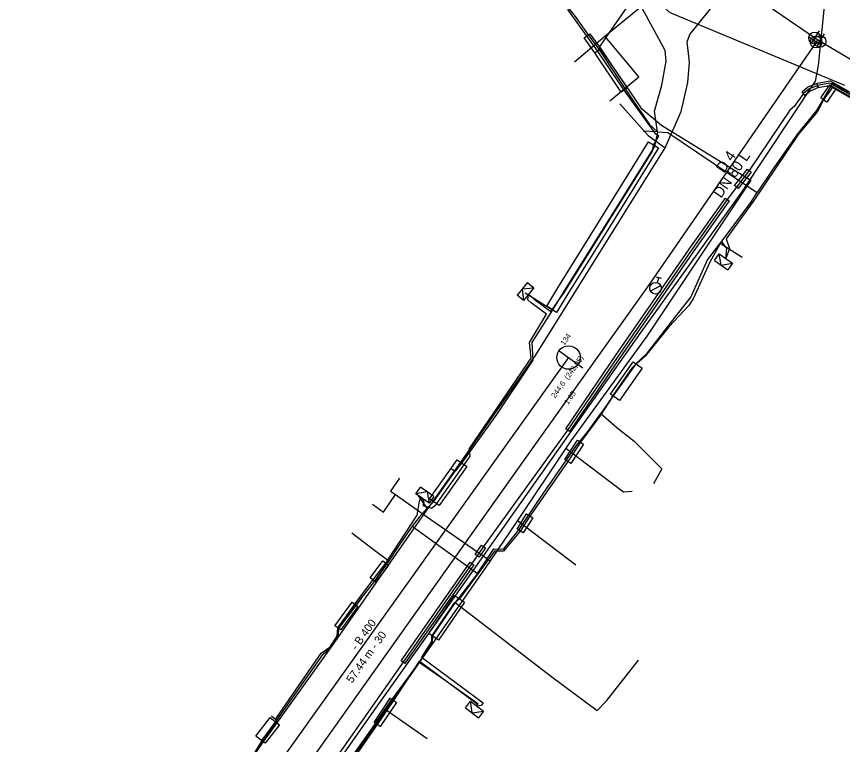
# Model space of a CAD drawing. Extents: x -600636 to -600148, y -1203980 to -1203569.
# Drawn here: x -600384.3 to -600313.9, y -1203740.1 to -1203678.1 of the extents above; entities that cross this region are included whole.
import ezdxf

# ---------------------------------------------------------------- set-up
doc = ezdxf.new("R2010")
doc.units = 0
for name, color, linetype in [('Cetin zam průběh', 7, 'Continuous'), ('EON podzemní NN', 7, 'Continuous'), ('EON podzemní VN', 7, 'Continuous'), ('GasNet NTL', 7, 'Continuous'), ('Implicitní', 7, 'Continuous'), ('VaK Břeclav_kanalizace', 7, 'Continuous'), ('Vak Břeclav_vodovod', 7, 'Continuous'), ('Vrstva 9', 7, 'Continuous')]:
    doc.layers.add(name, color=color, linetype=linetype)

# ---------------------------------------------------------------- blocks, each defined once
blk = doc.blocks.new('NN630')
at = {"layer": 'Vrstva 9'}
for points in [[(-0.003, -0.7), (-0.703, 0)], [(-0.703, -0.7), (-0.703, 0), (0.697, 0), (0.697, -0.7)], [(-0.703, -0.7), (0.697, -0.7)], [(-0.003, -0.7), (0.697, 0)]]:
    blk.add_lwpolyline(points, dxfattribs=at)
blk = doc.blocks.new('MoSymbol 2')
at = {"layer": 'Implicitní'}
blk.add_line((0, 0.0005), (0, -0.00075), dxfattribs=at)
blk.add_circle((0, 0), 0.0005, dxfattribs=at)
blk = doc.blocks.new('MoSymbol 3')
at = {"layer": 'Implicitní'}
for p, q in [((-0.000225, 0.00095), (0.000225, 0.00095)), ((0, 0.00095), (0, 0.0005)), ((-0.000365, -0.000365), (0.000365, 0.000365))]:
    blk.add_line(p, q, dxfattribs=at)
blk.add_circle((0, 0), 0.0005, dxfattribs=at)

msp = doc.modelspace()

# ---------------------------------------------------------------- linework, layer by layer
at = {"layer": 'Cetin zam průběh'}
for points in [[(-600329.02, -1203689.27), (-600327.65, -1203686.16), (-600327.07, -1203683.69), (-600326.94, -1203681.95), (-600327.13, -1203680.22), (-600326.9, -1203679.6), (-600320.9, -1203672.11), (-600319.87, -1203671.25), (-600312.14, -1203676.45), (-600307.68, -1203679.27), (-600299.7, -1203684.11), (-600292.77, -1203688.32), (-600284.45, -1203693.32), (-600273.46, -1203699.98), (-600262.73, -1203706.4), (-600257.97, -1203709.2), (-600243.31, -1203717.93), (-600240.56, -1203720.13), (-600238.73, -1203718.32)], [(-600341.99, -1203672.1), (-600339.02, -1203675.1), (-600336.67, -1203678.06), (-600335.49, -1203679.73), (-600334.6, -1203680.94), (-600332.38, -1203684.29), (-600330.34, -1203687.27), (-600329.66, -1203687.89)], [(-600329.66, -1203687.89), (-600329.92, -1203686.15), (-600329.28, -1203683.93), (-600328.92, -1203681.87), (-600329, -1203680.95), (-600330.94, -1203677.41), (-600331.52, -1203676.9)], [(-600335.49, -1203679.73), (-600334.6, -1203680.94)], [(-600334.6, -1203680.94), (-600332.38, -1203684.29)], [(-600291.91, -1203697.34), (-600294.89, -1203695.51), (-600296.18, -1203694.98), (-600299.85, -1203692.83), (-600301.61, -1203691.58), (-600303.13, -1203690.66), (-600304.86, -1203689.65), (-600306.01, -1203688.96), (-600312.14, -1203685.36), (-600314.73, -1203683.76), (-600316.09, -1203686.08)], [(-600332.86, -1203685.5), (-600330.45, -1203688.2), (-600329.02, -1203689.27)], [(-600316.09, -1203686.08), (-600317.72, -1203688.07), (-600319.94, -1203691.26), (-600321.15, -1203693.08)], [(-600329.66, -1203687.89), (-600329.93, -1203689.16), (-600334.23, -1203696.05), (-600337.61, -1203701.47), (-600338.62, -1203703.09)], [(-600329.66, -1203687.89), (-600330.88, -1203687.85)], [(-600329.66, -1203687.89), (-600328.78, -1203687.96), (-600322.25, -1203692.35), (-600321.15, -1203693.08)], [(-600328.78, -1203687.96), (-600322.25, -1203692.35)], [(-600448.32, -1203764.77), (-600445.41, -1203766.9), (-600434.97, -1203774.92), (-600422.32, -1203783.12), (-600413.93, -1203789.04), (-600405.18, -1203794.93), (-600400.25, -1203797.98), (-600398.96, -1203798.36), (-600397.12, -1203797.36), (-600388.96, -1203781.95), (-600378.33, -1203762.13), (-600375.93, -1203758.23), (-600373.1, -1203754.01), (-600370.24, -1203749.96), (-600363.35, -1203740.04), (-600357.38, -1203731.69), (-600349.33, -1203720.15), (-600345.8, -1203715.19), (-600340.07, -1203706.96), (-600329.02, -1203689.27)], [(-600329.93, -1203689.16), (-600334.23, -1203696.05)], [(-600324.32, -1203697.42), (-600321.71, -1203693.92), (-600321.15, -1203693.08)], [(-600324.32, -1203697.42), (-600325.2, -1203699.01), (-600326.63, -1203702.13)], [(-600322.43, -1203698.61), (-600324.32, -1203697.42)], [(-600340.96, -1203701.64), (-600338.62, -1203703.09)], [(-600337.61, -1203701.47), (-600338.62, -1203703.09)], [(-600326.63, -1203702.13), (-600327, -1203702.72), (-600328.66, -1203704.49), (-600330.72, -1203707.02), (-600331.77, -1203707.97), (-600333.55, -1203710.56), (-600334.48, -1203711.92)], [(-600338.62, -1203703.09), (-600340.39, -1203705.86), (-600340.29, -1203707.36), (-600343.45, -1203712.08), (-600346.39, -1203716.15), (-600346.93, -1203716.85)], [(-600333.55, -1203710.56), (-600331.77, -1203707.97)], [(-600345.02, -1203725.57), (-600343.61, -1203723.45), (-600342.8, -1203723.5), (-600341.47, -1203721.81), (-600339.64, -1203719.08), (-600336.56, -1203714.64), (-600335.67, -1203713.53), (-600334.48, -1203711.92)], [(-600334.48, -1203711.92), (-600333.14, -1203713.1), (-600331.65, -1203714.28), (-600329.3, -1203716.65), (-600330, -1203717.93)], [(-600348.77, -1203719.46), (-600346.93, -1203716.85), (-600346.39, -1203716.15)], [(-600347.22, -1203716.65), (-600346.93, -1203716.85)], [(-600349.3, -1203719.98), (-600348.77, -1203719.46), (-600346.93, -1203716.85)], [(-600349.3, -1203719.98), (-600350.05, -1203718.94)], [(-600349.3, -1203719.98), (-600349.98, -1203720.75), (-600350.59, -1203721.54)], [(-600350.59, -1203721.54), (-600351.64, -1203723.07)], [(-600350.59, -1203721.54), (-600345.02, -1203725.57)], [(-600350.59, -1203721.54), (-600345.02, -1203725.57)], [(-600355.72, -1203722.09), (-600353.92, -1203723.48), (-600352.59, -1203724.49)], [(-600351.64, -1203723.07), (-600352.59, -1203724.49)], [(-600362.14, -1203738.07), (-600358.19, -1203732.44), (-600357.54, -1203731.91), (-600356.89, -1203730.92), (-600356.8, -1203730.18), (-600354.93, -1203727.69), (-600353.8, -1203726.24), (-600352.59, -1203724.49)], [(-600352.59, -1203724.49), (-600353.8, -1203726.24)], [(-600345.02, -1203725.57), (-600346.92, -1203728.04)], [(-600354.93, -1203727.69), (-600356.8, -1203730.18)], [(-600346.92, -1203728.04), (-600348.83, -1203730.83), (-600348.92, -1203731.44), (-600349.98, -1203733.11)], [(-600348.83, -1203730.83), (-600346.92, -1203728.04)], [(-600346.92, -1203728.04), (-600338.68, -1203734.38), (-600334.81, -1203737.25), (-600333.97, -1203736.39), (-600331.29, -1203732.95)], [(-600349.98, -1203733.11), (-600352.35, -1203736.35), (-600353.65, -1203738.25), (-600357.31, -1203743.38), (-600359.31, -1203746.17), (-600359.98, -1203746.53), (-600361.18, -1203748.34)], [(-600349.98, -1203733.11), (-600348.14, -1203734.39), (-600346.78, -1203735.36), (-600344.99, -1203736.64), (-600345.13, -1203736.85)], [(-600353.65, -1203738.25), (-600352.35, -1203736.35)], [(-600362.59, -1203737.71), (-600362.14, -1203738.07)], [(-600371.33, -1203751.67), (-600367.69, -1203746.37), (-600365.25, -1203742.89), (-600363.56, -1203740.1), (-600363.39, -1203739.78), (-600362.14, -1203738.07)], [(-600362.14, -1203738.07), (-600363.39, -1203739.78)], [(-600365.25, -1203742.89), (-600363.56, -1203740.1)]]:
    msp.add_lwpolyline(points, dxfattribs=at)
at = {"layer": 'EON podzemní NN'}
for points in [[(-600364.409, -1203741.504), (-600363.365, -1203739.833), (-600362.171, -1203738.261), (-600362.154, -1203737.878), (-600358.34, -1203732.37), (-600357.58, -1203731.83), (-600356.98, -1203730.9), (-600356.92, -1203730.2), (-600355.15, -1203727.74), (-600353.93, -1203726.13), (-600352.83, -1203724.67), (-600352.64, -1203724.36), (-600350.16, -1203720.58), (-600349.974, -1203719.405), (-600349.918, -1203719.261), (-600349.71, -1203719.17), (-600349.578, -1203719.49), (-600349.688, -1203719.771), (-600348.944, -1203719.986), (-600348.538, -1203719.669), (-600346.141, -1203716.287), (-600345.646, -1203715.55), (-600345.687, -1203714.9), (-600340.43, -1203707.19), (-600340.58, -1203705.85), (-600339.125, -1203703.456), (-600340.432, -1203702.472), (-600340.728, -1203702.213), (-600340.66, -1203701.74), (-600340.18, -1203702.162), (-600338.756, -1203703.234), (-600337.583, -1203701.581), (-600330.091, -1203689.555), (-600330, -1203689.03), (-600329.55, -1203688.27), (-600329.79, -1203688.1), (-600332.51, -1203684.34), (-600334.77, -1203681), (-600337.32, -1203677.47)], [(-600300.1, -1203693.14), (-600300.09, -1203692.82), (-600302.356, -1203691.251), (-600303.624, -1203690.511), (-600305.35, -1203689.5), (-600311.54, -1203685.86), (-600314.7, -1203684.06), (-600315.49, -1203685.17), (-600316.007, -1203686.155), (-600317.63, -1203688.11), (-600321.5, -1203693.84), (-600323.385, -1203696.438)], [(-600323.385, -1203696.438), (-600323.817, -1203697.034), (-600323.521, -1203697.85), (-600323.824, -1203698.698), (-600323.753, -1203697.835), (-600324.207, -1203697.234), (-600325.017, -1203698.307)], [(-600325.017, -1203698.307), (-600325.386, -1203698.796), (-600326.82, -1203701.97), (-600328.814, -1203704.512), (-600330.617, -1203706.864), (-600331.49, -1203707.646), (-600333.526, -1203710.518), (-600334.519, -1203712.072), (-600336.22, -1203714.37), (-600337.32, -1203716), (-600340.56, -1203720.66), (-600341.38, -1203721.95), (-600342.79, -1203723.669), (-600343.55, -1203723.65), (-600346.55, -1203727.73), (-600347.052, -1203728.137), (-600348.942, -1203730.911), (-600348.932, -1203731.374), (-600349.779, -1203732.697), (-600344.525, -1203736.593), (-600344.695, -1203736.832), (-600345.04, -1203736.88), (-600345.051, -1203736.7), (-600349.996, -1203733.034), (-600352.18, -1203736.39), (-600353.56, -1203738.45), (-600357.2, -1203743.67)]]:
    msp.add_lwpolyline(points, dxfattribs=at)
for points in [[(-600335.925, -1203679.884), (-600335.429, -1203679.529), (-600334.505, -1203680.82), (-600335.011, -1203681.161)], [(-600335.011, -1203681.161), (-600334.505, -1203680.82), (-600332.249, -1203684.162), (-600332.754, -1203684.503)], [(-600314.955, -1203683.887), (-600314.443, -1203684.24), (-600315.216, -1203685.361), (-600315.728, -1203685.008)], [(-600330.418, -1203688.745), (-600329.562, -1203689.263), (-600333.895, -1203696.258), (-600337.308, -1203701.715), (-600338.28, -1203703.313), (-600339.108, -1203702.752), (-600338.16, -1203701.191), (-600334.737, -1203695.718)], [(-600331.743, -1203707.518), (-600330.967, -1203708.065), (-600332.905, -1203710.817), (-600333.681, -1203710.271)], [(-600336.476, -1203714.193), (-600335.962, -1203714.539), (-600337.061, -1203716.17), (-600337.571, -1203715.829)], [(-600346.738, -1203715.862), (-600345.921, -1203716.438), (-600348.279, -1203719.778), (-600349.094, -1203719.203)], [(-600340.822, -1203720.482), (-600340.299, -1203720.816), (-600341.122, -1203722.104), (-600341.641, -1203721.775)], [(-600353.075, -1203724.495), (-600352.596, -1203724.858), (-600353.693, -1203726.306), (-600354.171, -1203725.944)], [(-600355.717, -1203728.014), (-600355.226, -1203728.369), (-600356.679, -1203730.377), (-600357.17, -1203730.022)], [(-600346.964, -1203727.443), (-600346.136, -1203728.005), (-600348.334, -1203731.245), (-600349.154, -1203730.692)], [(-600352.459, -1203736.202), (-600351.936, -1203736.553), (-600353.317, -1203738.612), (-600353.836, -1203738.265)], [(-600362.708, -1203737.856), (-600361.914, -1203738.463), (-600363.116, -1203740.036), (-600363.911, -1203739.429)]]:
    msp.add_lwpolyline(points, close=True, dxfattribs=at)
at = {"layer": 'EON podzemní VN'}
for points in [[(-600366.95, -1203635.593), (-600366.181, -1203636.795), (-600358.381, -1203643.411), (-600344.954, -1203653.759), (-600330.827, -1203664.425), (-600321.645, -1203670.963), (-600317.713, -1203673.458), (-600315.791, -1203674.896), (-600315.293, -1203675.777), (-600315.944, -1203682.246), (-600316.226, -1203683.581), (-600322.501, -1203693.042), (-600331.079, -1203704.985), (-600348.911, -1203730.288), (-600354.208, -1203737.743), (-600361.516, -1203748.136), (-600365.138, -1203753.003), (-600368.824, -1203758.254), (-600375.091, -1203769.039), (-600381.398, -1203780.278), (-600382.49, -1203782.6), (-600383.25, -1203783.59)], [(-600313.007, -1203684.869), (-600314.967, -1203683.759), (-600316.007, -1203683.949), (-600316.757, -1203684.269), (-600317.207, -1203684.639), (-600317.997, -1203685.729), (-600318.367, -1203686.039), (-600321.837, -1203691.209), (-600322.927, -1203692.609), (-600323.707, -1203693.669), (-600326.587, -1203697.729), (-600333.047, -1203707.069), (-600337.327, -1203713.329), (-600344.497, -1203723.269), (-600345.047, -1203724.049), (-600345.487, -1203724.709), (-600351.367, -1203733.129), (-600357.517, -1203741.909)]]:
    msp.add_lwpolyline(points, dxfattribs=at)
for points in [[(-600313.105, -1203685.043), (-600315.002, -1203683.969), (-600315.971, -1203684.146), (-600316.043, -1203683.752), (-600314.931, -1203683.549), (-600312.908, -1203684.695)], [(-600316.085, -1203683.765), (-600315.928, -1203684.133), (-600316.652, -1203684.442), (-600317.08, -1203684.793), (-600317.334, -1203684.484), (-600316.861, -1203684.096)], [(-600321.994, -1203691.086), (-600321.679, -1203691.332), (-600322.769, -1203692.732), (-600323.084, -1203692.486)], [(-600323.87, -1203693.553), (-600323.543, -1203693.785), (-600326.423, -1203697.844), (-600332.882, -1203707.182), (-600337.162, -1203713.442), (-600337.492, -1203713.216), (-600333.211, -1203706.956), (-600326.75, -1203697.614)], [(-600344.66, -1203723.154), (-600344.333, -1203723.384), (-600344.883, -1203724.164), (-600345.21, -1203723.934)], [(-600345.651, -1203724.594), (-600345.323, -1203724.823), (-600351.203, -1203733.243), (-600351.531, -1203733.014)]]:
    msp.add_lwpolyline(points, close=True, dxfattribs=at)
at = {"layer": 'GasNet NTL'}
for points in [[(-600309.24, -1203678.67), (-600322.08, -1203669.74), (-600324.1, -1203669.99), (-600324.38, -1203670.02), (-600324.57, -1203670.3), (-600329.11, -1203676.87), (-600329.27, -1203677.14), (-600328.72, -1203677.64), (-600328.46, -1203677.78), (-600313.71, -1203683.92)], [(-600331.63, -1203676.31), (-600333.84, -1203679.52), (-600334.07, -1203679.86), (-600334.63, -1203680.67), (-600332.29, -1203684.08), (-600331.07, -1203685.85), (-600329.31, -1203687.34), (-600321.69, -1203692.03)], [(-600330.12, -1203676.43), (-600333.84, -1203679.52), (-600334.14, -1203679.77)], [(-600334.14, -1203679.77), (-600336.75, -1203681.95)], [(-600334.14, -1203679.77), (-600331.26, -1203683.23), (-600333.72, -1203685.28)], [(-600321.69, -1203692.03), (-600330.58, -1203705.33), (-600337.06, -1203714.26), (-600337.47, -1203714.88), (-600341.61, -1203721.03), (-600343.93, -1203724.48), (-600344.29, -1203725.01), (-600352.8, -1203737.19), (-600355.42, -1203740.94), (-600356.36, -1203742.04), (-600356.56, -1203742.28), (-600357.37, -1203743.06), (-600358.82, -1203744.14), (-600359.04, -1203744.31), (-600359.16, -1203744.4), (-600365.08, -1203752.77), (-600365.18, -1203752.95), (-600368.57, -1203759.1), (-600375.05, -1203770.85), (-600375.18, -1203771.08)], [(-600337.47, -1203714.88), (-600332.57, -1203718.61), (-600331.83, -1203718.55)], [(-600351.67, -1203717.44), (-600352.44, -1203718.54), (-600352.01, -1203718.84)], [(-600353.98, -1203719.66), (-600353.04, -1203720.32), (-600352.01, -1203718.84)], [(-600352.01, -1203718.84), (-600349.36, -1203720.69), (-600344.44, -1203724.12), (-600343.93, -1203724.48)], [(-600341.61, -1203721.03), (-600336.63, -1203724.81)], [(-600352.8, -1203737.19), (-600349.31, -1203739.63)]]:
    msp.add_lwpolyline(points, dxfattribs=at)
at = {"layer": 'VaK Břeclav_kanalizace'}
msp.add_line((-600337.248, -1203707.145), (-600370.65, -1203753.88), dxfattribs=at)
at = {"layer": 'Vak Břeclav_vodovod'}
for p, q in [((-600316.022, -1203680.054), (-600316.256, -1203679.894)), ((-600316.022, -1203680.054), (-600316.133, -1203680.243)), ((-600315.791, -1203680.191), (-600316.022, -1203680.054)), ((-600316.133, -1203680.243), (-600330.382, -1203700.926))]:
    msp.add_line(p, q, dxfattribs=at)
for points in [[(-600316.256, -1203679.894), (-600332.434, -1203668.792), (-600354.837, -1203651.734), (-600377.846, -1203634.299)], [(-600236.89, -1203728.365), (-600242.377, -1203724.953), (-600264, -1203711.729), (-600288.949, -1203696.473), (-600297.916, -1203690.812), (-600315.791, -1203680.191)], [(-600330.382, -1203700.926), (-600340.064, -1203714.494), (-600360.044, -1203742.638), (-600371.815, -1203758.94), (-600385.686, -1203786.009), (-600395.742, -1203804.116)]]:
    msp.add_lwpolyline(points, dxfattribs=at)

# ---------------------------------------------------------------- block references
at = {"layer": 'EON podzemní NN'}
for p, rotation in [((-600323.824, -1203698.698), -34.76214450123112), ((-600340.66, -1203701.74), -129.16428899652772), ((-600349.71, -1203719.17), 144.98242772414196), ((-600345.04, -1203736.88), -37.60859440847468)]:
    msp.add_blockref('NN630', p, dxfattribs=dict(at, rotation=rotation))
at = {"layer": 'VaK Břeclav_kanalizace', "xscale": 1999.750031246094, "yscale": 1999.7500312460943, "rotation": 54.44620557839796}
msp.add_blockref('MoSymbol 2', (-600337.248, -1203707.145), dxfattribs=at)
at = {"layer": 'Vak Břeclav_vodovod', "yscale": 999.8750156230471}
for name, p, xscale, rotation in [('MoSymbol 2', (-600316.133, -1203680.243), 999.875015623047, -122.49482217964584), ('MoSymbol 2', (-600316.256, -1203679.894), 999.8750156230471, 145.54188289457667), ('MoSymbol 2', (-600315.791, -1203680.191), 999.8750156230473, 149.2825871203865), ('MoSymbol 3', (-600329.824, -1203701.236), 999.8750156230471, -16.440379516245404)]:
    msp.add_blockref(name, p, dxfattribs=dict(at, xscale=xscale, rotation=rotation))

# ---------------------------------------------------------------- texts
at = {"layer": 'VaK Břeclav_kanalizace'}
for s, height, p in [('134', 0.4549, (-600337.613, -1203706.156)), ('244,6  (242,95)', 0.45494, (-600338.402, -1203710.642)), ('1.65', 0.4549, (-600337.3, -1203711.2)), ('- B 400', 0.6824, (-600355.328, -1203732.16)), ('57.44 m - 30', 0.68241, (-600355.718, -1203734.961))]:
    msp.add_text(s, height=height, rotation=54.44621, dxfattribs=at).set_placement(p)
at = {"layer": 'Vak Břeclav_vodovod'}
for s, p in [('DN 80 L', (-600324.241, -1203693.616)), ('D 4', (-600323.995, -1203691.479))]:
    msp.add_text(s, height=0.9099, rotation=55.43614, dxfattribs=at).set_placement(p)

doc.saveas('drawing.dxf')
